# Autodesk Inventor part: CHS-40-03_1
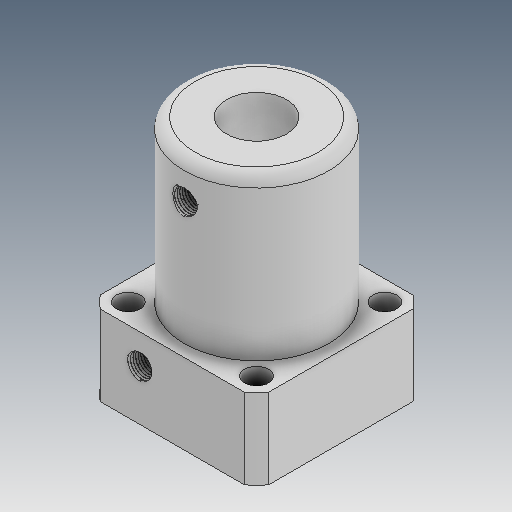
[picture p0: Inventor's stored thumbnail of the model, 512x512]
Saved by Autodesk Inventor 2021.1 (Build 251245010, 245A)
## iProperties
Created: 2019-04
Part Number: CHS-40-03_1
Material: Ogólny
Document SubType Name: Modeling
Designer: user
Density: 1 g/cm^3
Appearance: Domyślna
Author: user
Revision Number: ÈÎºÎ
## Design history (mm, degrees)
feature "ÊäÈë1"
node "Bryła1"
